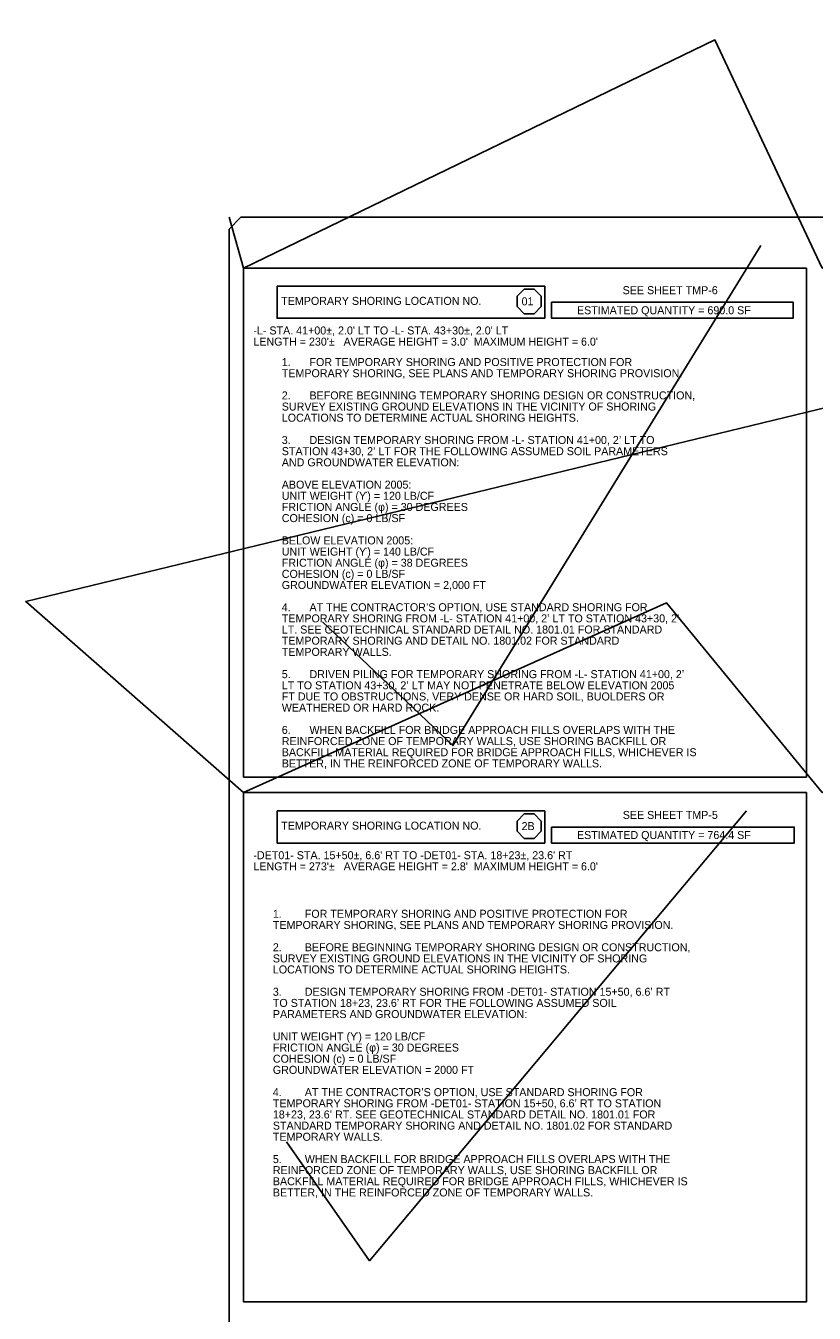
# Model space of a CAD drawing. Extents: x 2487012 to 2497594, y 369516 to 371986.
# Drawn here: x 2488843 to 2489515, y 370349 to 371445 of the extents above; entities that cross this region are included whole.
import ezdxf

# ---------------------------------------------------------------- set-up
doc = ezdxf.new("R2010")
doc.units = 0
for name, color, linetype in [('Scratch_Level_2', 7, 'Continuous'), ('Scratch_Level_3', 7, 'Continuous'), ('Scratch_Level_6', 7, 'Continuous'), ('TC LABEL TEMP SHORING', 7, 'Continuous'), ('TC SHEET BORDER LINE THIN', 7, 'Continuous'), ('TC SHEET LAYOUT SHAPE', 7, 'Continuous'), ('TC SHEET TEXT', 7, 'Continuous')]:
    doc.layers.add(name, color=color, linetype=linetype)

msp = doc.modelspace()

# ---------------------------------------------------------------- linework, layer by layer
at = {"layer": 'Scratch_Level_2'}
for points in [[(2489096.2, 370937.9), (2489207.2, 370832.4), (2489469.6, 371258.3)], [(2489065.4, 370495), (2489136.2, 370393.6), (2489457.2, 370776.7)]]:
    msp.add_lwpolyline(points, dxfattribs=at)
at = {"layer": 'Scratch_Level_3'}
msp.add_line((2489016.6, 371282.3), (2489016.6, 371282.3), dxfattribs=at)
at = {"layer": 'Scratch_Level_6'}
msp.add_lwpolyline([(2489016.6, 371282.3), (2489028.9, 371239.1), (2489430.4, 371433.4), (2489521.8, 371239.1), (2489836.5, 371445.4), (2490014.7, 371239.1), (2488843.3, 370955.2), (2489028.9, 370792.3), (2489389.2, 370953.9), (2489521.8, 370792.3), (2489877.8, 370924.6), (2490014.7, 370792.3)], dxfattribs=at)
at = {"layer": 'TC LABEL TEMP SHORING'}
for p, q in [((2489267.8, 371221.2), (2489261.8, 371215)), ((2489276.4, 371221.2), (2489267.8, 371221.2)), ((2489282.5, 371215), (2489276.4, 371221.2)), ((2489261.8, 371215), (2489261.8, 371206.3)), ((2489282.5, 371206.3), (2489282.5, 371215)), ((2489261.8, 371206.3), (2489267.8, 371200.1)), ((2489267.8, 371200.1), (2489276.4, 371200.1)), ((2489276.4, 371200.1), (2489282.5, 371206.3)), ((2489267.8, 370774.3), (2489261.8, 370768.1)), ((2489276.4, 370774.3), (2489267.8, 370774.3)), ((2489282.5, 370768.1), (2489276.4, 370774.3)), ((2489261.8, 370768.1), (2489261.8, 370759.4)), ((2489282.5, 370759.4), (2489282.5, 370768.1)), ((2489261.8, 370759.4), (2489267.8, 370753.2)), ((2489267.8, 370753.2), (2489276.4, 370753.2)), ((2489276.4, 370753.2), (2489282.5, 370759.4))]:
    msp.add_line(p, q, dxfattribs=at)
at = {"layer": 'TC SHEET BORDER LINE THIN'}
for points in [[(2489028.9, 371239.1), (2489508.3, 371239.1), (2489508.3, 370805.5), (2489028.9, 370805.5)], [(2489057.4, 371223.5), (2489285.4, 371223.5), (2489285.4, 371196.3), (2489057.4, 371196.3)], [(2489291.2, 371209.9), (2489497, 371209.9), (2489497, 371196.3), (2489291.2, 371196.3)], [(2489028.9, 370792.3), (2489508.3, 370792.3), (2489508.3, 370358.6), (2489028.9, 370358.6)], [(2489057.4, 370776.7), (2489285.4, 370776.7), (2489285.4, 370749.4), (2489057.4, 370749.4)], [(2489291.2, 370763), (2489498, 370763), (2489498, 370749.4), (2489291.2, 370749.4)]]:
    msp.add_lwpolyline(points, close=True, dxfattribs=at)
at = {"layer": 'TC SHEET LAYOUT SHAPE'}
msp.add_lwpolyline([(2489016.6, 370690.8), (2489016.6, 371000.2), (2489016.6, 371272.3), (2489026.6, 371282.3), (2489469.6, 371282.3), (2489940.6, 371282.3), (2490261.6, 371282.3), (2490261.6, 371202.3), (2490346.6, 371202.3), (2490346.6, 371250.3), (2490506.6, 371250.3), (2490506.6, 370915.3), (2490506.6, 370636.1), (2490506.6, 370384.8), (2490151.6, 370384.8), (2490151.6, 370242.3), (2489778.4, 370242.3), (2489608.9, 370242.3), (2489256.1, 370242.3), (2489016.6, 370242.3)], close=True, dxfattribs=at)

# ---------------------------------------------------------------- texts
at = {"layer": 'TC LABEL TEMP SHORING'}
for s, p in [('01', (2489265.7, 371207.3)), ('2B', (2489265.7, 370760.4))]:
    msp.add_text(s, height=6.81, dxfattribs=at).set_placement(p)
at = {"layer": 'TC SHEET BORDER LINE THIN'}
for s, height, p in [('1.', 6.81, (2489061.4, 371155.6)), ('FOR TEMPORARY SHORING AND POSITIVE PROTECTION FOR ', 6.814, (2489085, 371155.6)), ('TEMPORARY SHORING, SEE PLANS AND TEMPORARY SHORING PROVISION.', 6.814, (2489061.4, 371146.1)), ('2.', 6.81, (2489061.4, 371127.2)), ('BEFORE BEGINNING TEMPORARY SHORING DESIGN OR CONSTRUCTION, ', 6.814, (2489085, 371127.2)), ('SURVEY EXISTING GROUND ELEVATIONS IN THE VICINITY OF SHORING ', 6.814, (2489061.4, 371117.7)), ('LOCATIONS TO DETERMINE ACTUAL SHORING HEIGHTS.', 6.814, (2489061.4, 371108.2)), ('3.', 6.81, (2489061.4, 371089.2)), ('DESIGN TEMPORARY SHORING FROM -L- STATION 41+00, 2’ LT TO ', 6.814, (2489085, 371089.2)), ('STATION 43+30, 2’ LT FOR THE FOLLOWING ASSUMED SOIL PARAMETERS ', 6.814, (2489061.4, 371079.7)), ('AND GROUNDWATER ELEVATION:', 6.814, (2489061.4, 371070.2)), ('ABOVE ELEVATION 2005:', 6.814, (2489061.4, 371051.2)), ('UNIT WEIGHT (ϒ) = 120 LB/CF', 6.814, (2489061.4, 371041.7)), ('FRICTION ANGLE (φ) = 30 DEGREES', 6.814, (2489061.4, 371032.2)), ('COHESION (c) = 0 LB/SF', 6.814, (2489061.4, 371022.7)), ('BELOW ELEVATION 2005:', 6.814, (2489061.4, 371003.7)), ('UNIT WEIGHT (ϒ) = 140 LB/CF', 6.814, (2489061.4, 370994.2)), ('FRICTION ANGLE (φ) = 38 DEGREES', 6.814, (2489061.4, 370984.7)), ('COHESION (c) = 0 LB/SF', 6.814, (2489061.4, 370975.2)), ('GROUNDWATER ELEVATION = 2,000 FT', 6.814, (2489061.4, 370965.7)), ('4.', 6.81, (2489061.4, 370946.8)), ('AT THE CONTRACTOR’S OPTION, USE STANDARD SHORING FOR ', 6.814, (2489085, 370946.8)), ('TEMPORARY SHORING FROM -L- STATION 41+00, 2’ LT TO STATION 43+30, 2’ ', 6.814, (2489061.4, 370937.3)), ('TEMPORARY SHORING AND DETAIL NO. 1801.02 FOR STANDARD ', 6.814, (2489061.4, 370918.3)), ('LT. SEE GEOTECHNICAL STANDARD DETAIL NO. 1801.01 FOR STANDARD ', 6.814, (2489061.4, 370927.8)), ('TEMPORARY WALLS.', 6.814, (2489061.4, 370908.8)), ('5.', 6.81, (2489061.4, 370889.8)), ('DRIVEN PILING FOR TEMPORARY SHORING FROM -L- STATION 41+00, 2’ ', 6.814, (2489085, 370889.8)), ('LT TO STATION 43+30, 2’ LT MAY NOT PENETRATE BELOW ELEVATION 2005 ', 6.814, (2489061.4, 370880.3)), ('FT DUE TO OBSTRUCTIONS, VERY DENSE OR HARD SOIL, BUOLDERS OR ', 6.814, (2489061.4, 370870.8)), ('WEATHERED OR HARD ROCK.', 6.814, (2489061.4, 370861.3)), ('6.', 6.81, (2489061.4, 370842.3)), ('WHEN BACKFILL FOR BRIDGE APPROACH FILLS OVERLAPS WITH THE ', 6.814, (2489085, 370842.3)), ('REINFORCED ZONE OF TEMPORARY WALLS, USE SHORING BACKFILL OR ', 6.814, (2489061.4, 370832.8)), ('BACKFILL MATERIAL REQUIRED FOR BRIDGE APPROACH FILLS, WHICHEVER IS ', 6.814, (2489061.4, 370823.3)), ('BETTER, IN THE REINFORCED ZONE OF TEMPORARY WALLS.', 6.814, (2489061.4, 370813.8)), ('1.', 6.81, (2489053.8, 370685.7)), ('FOR TEMPORARY SHORING AND POSITIVE PROTECTION FOR ', 6.814, (2489081, 370685.7)), ('TEMPORARY SHORING, SEE PLANS AND TEMPORARY SHORING PROVISION.', 6.814, (2489053.8, 370676.2)), ('2.', 6.81, (2489053.8, 370657.2)), ('BEFORE BEGINNING TEMPORARY SHORING DESIGN OR CONSTRUCTION, ', 6.814, (2489081, 370657.2)), ('SURVEY EXISTING GROUND ELEVATIONS IN THE VICINITY OF SHORING ', 6.814, (2489053.8, 370647.7)), ('LOCATIONS TO DETERMINE ACTUAL SHORING HEIGHTS.', 6.814, (2489053.8, 370638.3)), ('3.', 6.81, (2489053.8, 370619.3)), ('DESIGN TEMPORARY SHORING FROM -DET01- STATION 15+50, 6.6’ RT ', 6.814, (2489081, 370619.3)), ('TO STATION 18+23, 23.6’ RT FOR THE FOLLOWING ASSUMED SOIL ', 6.814, (2489053.8, 370609.8)), ('PARAMETERS AND GROUNDWATER ELEVATION:', 6.814, (2489053.8, 370600.3)), ('UNIT WEIGHT (ϒ) = 120 LB/CF', 6.814, (2489053.8, 370581.3)), ('FRICTION ANGLE (φ) = 30 DEGREES', 6.814, (2489053.8, 370571.8)), ('COHESION (c) = 0 LB/SF', 6.814, (2489053.8, 370562.3)), ('GROUNDWATER ELEVATION = 2000 FT', 6.814, (2489053.8, 370552.8)), ('4.', 6.81, (2489053.8, 370533.8)), ('TEMPORARY SHORING FROM -DET01- STATION 15+50, 6.6’ RT TO STATION ', 6.814, (2489053.8, 370524.3)), ('AT THE CONTRACTOR’S OPTION, USE STANDARD SHORING FOR ', 6.814, (2489081, 370533.8)), ('18+23, 23.6’ RT. SEE GEOTECHNICAL STANDARD DETAIL NO. 1801.01 FOR ', 6.814, (2489053.8, 370514.8)), ('STANDARD TEMPORARY SHORING AND DETAIL NO. 1801.02 FOR STANDARD ', 6.814, (2489053.8, 370505.3)), ('TEMPORARY WALLS.', 6.814, (2489053.8, 370495.8)), ('5.', 6.81, (2489053.8, 370476.8)), ('WHEN BACKFILL FOR BRIDGE APPROACH FILLS OVERLAPS WITH THE ', 6.814, (2489081, 370476.8)), ('REINFORCED ZONE OF TEMPORARY WALLS, USE SHORING BACKFILL OR ', 6.814, (2489053.8, 370467.4)), ('BACKFILL MATERIAL REQUIRED FOR BRIDGE APPROACH FILLS, WHICHEVER IS ', 6.814, (2489053.8, 370457.9)), ('BETTER, IN THE REINFORCED ZONE OF TEMPORARY WALLS.', 6.814, (2489053.8, 370448.4))]:
    msp.add_text(s, height=height, dxfattribs=at).set_placement(p)
at = {"layer": 'TC SHEET TEXT'}
for s, p in [('SEE SHEET TMP-6', (2489351.8, 371216.8)), ('TEMPORARY SHORING LOCATION NO.', (2489060.9, 371207.7)), ('ESTIMATED QUANTITY = 690.0 SF', (2489312.9, 371199.7)), ("-L- STA. 41+00±, 2.0' LT TO -L- STA. 43+30±, 2.0' LT", (2489037.2, 371182.5)), ("LENGTH = 230'±   AVERAGE HEIGHT = 3.0'  MAXIMUM HEIGHT = 6.0'", (2489037.2, 371173)), ('SEE SHEET TMP-5', (2489351.9, 370769.9)), ('TEMPORARY SHORING LOCATION NO.', (2489060.9, 370760.8)), ('ESTIMATED QUANTITY = 764.4 SF', (2489312.9, 370752.8)), ("-DET01- STA. 15+50±, 6.6' RT TO -DET01- STA. 18+23±, 23.6' RT", (2489037.2, 370735.6)), ("LENGTH = 273'±   AVERAGE HEIGHT = 2.8'  MAXIMUM HEIGHT = 6.0'", (2489037.2, 370726.1))]:
    msp.add_text(s, height=6.814, dxfattribs=at).set_placement(p)

doc.saveas('drawing.dxf')
